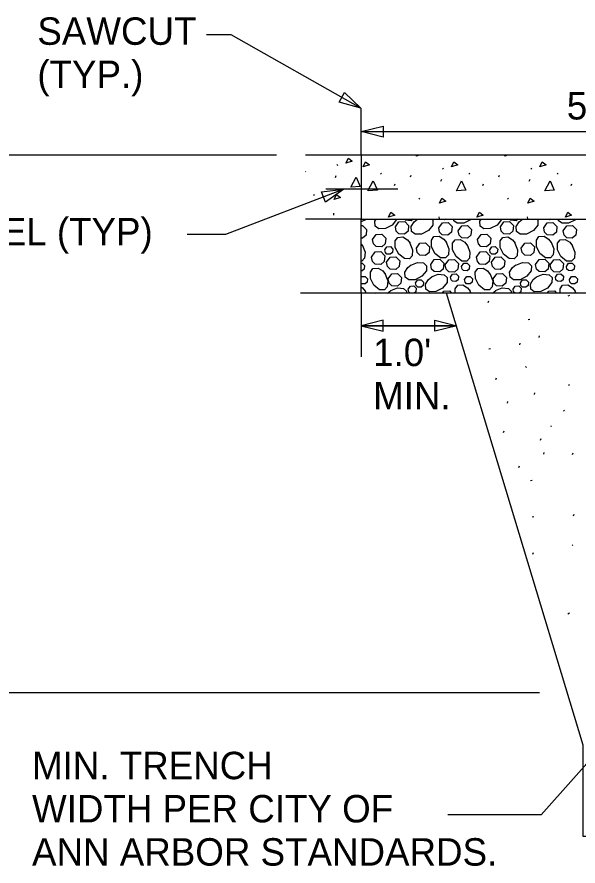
# Model space of a CAD drawing. Extents: x 9992 to 10079.1, y 10009.9 to 10072.5.
# Drawn here: x 10011.77 to 10033.1, y 10036.68 to 10068.99 of the extents above; entities that cross this region are included whole.
import ezdxf

# ---------------------------------------------------------------- set-up
doc = ezdxf.new("R2010")
doc.units = 0
for name, color, linetype in [('Default', 7, 'Continuous'), ('G-ANNO-TEXT', 7, 'Continuous'), ('G-DETL-LINE', 7, 'Continuous'), ('G-DETL-OTLN', 7, 'Continuous'), ('G-DETL-PATT', 7, 'Continuous')]:
    doc.layers.add(name, color=color, linetype=linetype)

# ---------------------------------------------------------------- blocks, each defined once
blk = doc.blocks.new('TERARR')
at = {"layer": 'Default'}
blk.add_lwpolyline([(-0.667, 0.167), (0, 0), (-0.667, -0.167)], close=True, dxfattribs=at)

msp = doc.modelspace()

# ---------------------------------------------------------------- linework, layer by layer
at = {"layer": 'Default'}
for p, q in [((10022.737, 10063.09), (10022.744, 10063.106)), ((10031.165, 10061.379), (10031.172, 10061.312))]:
    msp.add_line(p, q, dxfattribs=at)
for points in [[(10026.952, 10063.687), (10026.959, 10063.733)], [(10027.053, 10063.733), (10026.959, 10063.69)], [(10026.986, 10061.285), (10027.007, 10061.294)], [(10030.818, 10061.294), (10030.747, 10061.234), (10030.533, 10061.25), (10030.488, 10061.294)], [(10030.974, 10061.285), (10030.996, 10061.294)], [(10032.049, 10061.294), (10032.013, 10061.264), (10031.799, 10061.279), (10031.784, 10061.294)], [(10024.858, 10060.348), (10024.909, 10060.285)], [(10025.417, 10058.479), (10025.548, 10058.486), (10025.555, 10058.479)], [(10029.405, 10058.479), (10029.536, 10058.486), (10029.543, 10058.479)]]:
    msp.add_lwpolyline(points, dxfattribs=at)
at = {"layer": 'G-ANNO-TEXT'}
for p, q in [((10024.858, 10063.733), (10024.858, 10065.518)), ((10024.858, 10064.626), (10048.203, 10064.626)), ((9996.263, 10063.735), (10021.636, 10063.735)), ((10024.858, 10063.733), (10022.737, 10063.733)), ((10024.858, 10061.294), (10022.737, 10061.294)), ((10024.858, 10058.479), (10022.551, 10058.479)), ((10024.858, 10058.479), (10024.858, 10056.06)), ((10028.49, 10057.236), (10024.858, 10057.236)), ((10024.858, 10057.236), (10028.383, 10057.236)), ((9996.009, 10043.279), (10031.629, 10043.279))]:
    msp.add_line(p, q, dxfattribs=at)
for points in [[(10024.843, 10065.517), (10019.914, 10068.31), (10018.978, 10068.31)], [(10024.198, 10062.439), (10019.699, 10060.708), (10018.236, 10060.708)], [(10034.052, 10041.283), (10031.691, 10038.635), (10028.143, 10038.635)]]:
    msp.add_lwpolyline(points, dxfattribs=at)
at = {"layer": 'G-DETL-LINE'}
msp.add_line((10026.251, 10062.439), (10023.514, 10062.439), dxfattribs=at)
msp.add_lwpolyline([(10024.858, 10061.294), (10048.226, 10061.294), (10048.226, 10058.479), (10024.858, 10058.479)], close=True, dxfattribs=at)
at = {"layer": 'G-DETL-OTLN'}
msp.add_lwpolyline([(10024.858, 10061.294), (10048.203, 10061.294), (10048.203, 10063.733), (10024.858, 10063.733)], close=True, dxfattribs=at)
msp.add_lwpolyline([(10045.467, 10058.479), (10040.274, 10041.283), (10040.274, 10037.801), (10033.297, 10037.801), (10033.297, 10041.283), (10028.104, 10058.479)], dxfattribs=at)
at = {"layer": 'G-DETL-PATT'}
for p, q in [((10023.934, 10063.374), (10023.964, 10063.33)), ((10027.943, 10063.235), (10027.973, 10063.19)), ((10031.303, 10063.235), (10031.333, 10063.19)), ((10023.877, 10062.883), (10023.907, 10062.95)), ((10025.589, 10063.045), (10025.618, 10063.001)), ((10026.723, 10062.899), (10026.753, 10062.966)), ((10027.887, 10062.744), (10027.917, 10062.811)), ((10028.948, 10063.045), (10028.978, 10063.001)), ((10030.083, 10062.899), (10030.113, 10062.966)), ((10031.246, 10062.744), (10031.276, 10062.811)), ((10032.307, 10063.045), (10032.337, 10063.001)), ((10026.119, 10062.572), (10026.149, 10062.639)), ((10029.479, 10062.572), (10029.509, 10062.639)), ((10032.838, 10062.572), (10032.868, 10062.639)), ((10023.042, 10062.234), (10023.072, 10062.189)), ((10027.052, 10062.095), (10027.081, 10062.05)), ((10030.411, 10062.095), (10030.441, 10062.05)), ((10023.796, 10061.518), (10023.804, 10061.451)), ((10027.806, 10061.379), (10027.813, 10061.312)), ((10032.774, 10058.393), (10032.711, 10058.362)), ((10029.681, 10058.122), (10029.702, 10058.185)), ((10031.269, 10057.474), (10031.204, 10057.46)), ((10031.616, 10056.787), (10031.637, 10056.85)), ((10029.774, 10056.363), (10029.71, 10056.349)), ((10030.882, 10056.514), (10030.903, 10056.577)), ((10031.135, 10055.654), (10031.103, 10055.685)), ((10029.974, 10055.198), (10029.995, 10055.261)), ((10032.774, 10054.968), (10032.743, 10055)), ((10031.44, 10054.623), (10031.461, 10054.686)), ((10030.413, 10054.292), (10030.434, 10054.355)), ((10032.585, 10053.994), (10032.554, 10054.026)), ((10032.056, 10053.428), (10032.082, 10053.414)), ((10032.082, 10053.414), (10032.094, 10053.4)), ((10030.268, 10053.173), (10030.289, 10053.236)), ((10031.675, 10052.88), (10031.696, 10052.943)), ((10031.792, 10052.354), (10031.813, 10052.417)), ((10032.894, 10052.345), (10032.915, 10052.407)), ((10030.853, 10051.847), (10030.874, 10051.91)), ((10031.357, 10051.346), (10031.292, 10051.332)), ((10031.416, 10049.972), (10031.351, 10049.957)), ((10032.924, 10050.005), (10032.945, 10050.068)), ((10032.9, 10048.876), (10032.869, 10048.907)), ((10031.382, 10048.553), (10031.403, 10048.616)), ((10032.774, 10046.299), (10032.711, 10046.268))]:
    msp.add_line(p, q, dxfattribs=at)
for points in [[(10024.276, 10063.426), (10024.366, 10063.613), (10024.515, 10063.501), (10024.276, 10063.426)], [(10024.926, 10063.287), (10025.016, 10063.474), (10025.165, 10063.362), (10024.926, 10063.287)], [(10028.285, 10063.287), (10028.375, 10063.474), (10028.524, 10063.362), (10028.285, 10063.287)], [(10030.312, 10063.687), (10030.318, 10063.733)], [(10030.412, 10063.733), (10030.319, 10063.69)], [(10031.645, 10063.287), (10031.734, 10063.474), (10031.884, 10063.362), (10031.645, 10063.287)], [(10024.463, 10062.51), (10024.664, 10062.89), (10024.821, 10062.54), (10024.47, 10062.51)], [(10025.113, 10062.371), (10025.314, 10062.751), (10025.471, 10062.401), (10025.12, 10062.371)], [(10028.472, 10062.371), (10028.673, 10062.751), (10028.83, 10062.401), (10028.479, 10062.371)], [(10031.831, 10062.371), (10032.033, 10062.751), (10032.189, 10062.401), (10031.839, 10062.371)], [(10023.825, 10062.04), (10023.915, 10062.226), (10024.064, 10062.115), (10023.825, 10062.04)], [(10027.835, 10061.901), (10027.924, 10062.087), (10028.073, 10061.975), (10027.835, 10061.901)], [(10031.194, 10061.901), (10031.284, 10062.087), (10031.433, 10061.975), (10031.194, 10061.901)], [(10025.897, 10061.368), (10025.987, 10061.554), (10026.136, 10061.442), (10025.897, 10061.368)], [(10029.257, 10061.368), (10029.346, 10061.554), (10029.495, 10061.442), (10029.257, 10061.368)], [(10032.616, 10061.368), (10032.705, 10061.554), (10032.854, 10061.442), (10032.616, 10061.368)], [(10025.043, 10061.294), (10025.024, 10061.27), (10024.858, 10061.187)], [(10026.202, 10061.294), (10026.202, 10061.276), (10026.034, 10061.062), (10025.774, 10060.932), (10025.53, 10060.928), (10025.392, 10061.025), (10025.379, 10061.22), (10025.426, 10061.294)], [(10026.156, 10061.005), (10026.292, 10061.198), (10026.508, 10061.21), (10026.659, 10061.054), (10026.637, 10060.836), (10026.503, 10060.724), (10026.29, 10060.74), (10026.189, 10060.837), (10026.156, 10061.005)], [(10026.83, 10061.294), (10026.758, 10061.234), (10026.545, 10061.25), (10026.499, 10061.294)], [(10027.547, 10061.294), (10027.583, 10061.26), (10027.579, 10061.071), (10027.411, 10060.857), (10027.152, 10060.727), (10026.907, 10060.723), (10026.769, 10060.82), (10026.756, 10061.015), (10026.868, 10061.19), (10026.996, 10061.292)], [(10028.061, 10061.294), (10028.024, 10061.264), (10027.811, 10061.279), (10027.796, 10061.294)], [(10027.805, 10060.967), (10027.941, 10061.16), (10028.157, 10061.172), (10028.307, 10061.016), (10028.286, 10060.798), (10028.152, 10060.687), (10027.938, 10060.702), (10027.838, 10060.799), (10027.805, 10060.967)], [(10029.031, 10061.294), (10029.012, 10061.27), (10028.753, 10061.14), (10028.508, 10061.136), (10028.371, 10061.233), (10028.366, 10061.294)], [(10030.191, 10061.294), (10030.19, 10061.276), (10030.022, 10061.062), (10029.763, 10060.932), (10029.518, 10060.928), (10029.38, 10061.025), (10029.367, 10061.22), (10029.415, 10061.294)], [(10030.145, 10061.005), (10030.28, 10061.198), (10030.497, 10061.21), (10030.647, 10061.054), (10030.625, 10060.836), (10030.492, 10060.724), (10030.278, 10060.74), (10030.177, 10060.837), (10030.145, 10061.005)], [(10031.536, 10061.294), (10031.571, 10061.26), (10031.568, 10061.071), (10031.4, 10060.857), (10031.14, 10060.727), (10030.895, 10060.723), (10030.758, 10060.82), (10030.745, 10061.015), (10030.856, 10061.19), (10030.984, 10061.292)], [(10031.793, 10060.967), (10031.929, 10061.16), (10032.145, 10061.172), (10032.296, 10061.016), (10032.274, 10060.798), (10032.14, 10060.687), (10031.927, 10060.702), (10031.826, 10060.799), (10031.794, 10060.967)], [(10033.02, 10061.294), (10033.001, 10061.27), (10032.741, 10061.14), (10032.497, 10061.136), (10032.359, 10061.233), (10032.355, 10061.294)], [(10024.858, 10061.051), (10024.909, 10061.054), (10025.06, 10060.898), (10025.038, 10060.68), (10024.904, 10060.568), (10024.858, 10060.572)], [(10028.546, 10060.849), (10028.681, 10061.042), (10028.898, 10061.054), (10029.048, 10060.898), (10029.026, 10060.68), (10028.893, 10060.568), (10028.679, 10060.584), (10028.579, 10060.681), (10028.546, 10060.849)], [(10032.534, 10060.849), (10032.67, 10061.042), (10032.886, 10061.054), (10033.037, 10060.898), (10033.015, 10060.68), (10032.881, 10060.568), (10032.668, 10060.584), (10032.567, 10060.681), (10032.534, 10060.849)], [(10025.287, 10060.521), (10025.423, 10060.714), (10025.639, 10060.726), (10025.79, 10060.57), (10025.768, 10060.352), (10025.634, 10060.241), (10025.421, 10060.256), (10025.32, 10060.354), (10025.288, 10060.521)], [(10026.71, 10060.385), (10026.81, 10060.132), (10026.79, 10059.899), (10026.685, 10059.788), (10026.496, 10059.792), (10026.281, 10059.96), (10026.152, 10060.219), (10026.147, 10060.464), (10026.245, 10060.602), (10026.44, 10060.615), (10026.614, 10060.503), (10026.716, 10060.375)], [(10028.087, 10060.418), (10028.188, 10060.164), (10028.168, 10059.932), (10028.062, 10059.821), (10027.873, 10059.824), (10027.659, 10059.992), (10027.529, 10060.252), (10027.525, 10060.497), (10027.622, 10060.634), (10027.817, 10060.647), (10027.992, 10060.536), (10028.094, 10060.408)], [(10028.89, 10060.295), (10028.991, 10060.041), (10028.971, 10059.809), (10028.866, 10059.698), (10028.677, 10059.701), (10028.462, 10059.869), (10028.332, 10060.129), (10028.328, 10060.374), (10028.426, 10060.511), (10028.621, 10060.524), (10028.795, 10060.413), (10028.897, 10060.285)], [(10029.276, 10060.521), (10029.411, 10060.714), (10029.628, 10060.726), (10029.778, 10060.57), (10029.756, 10060.352), (10029.623, 10060.241), (10029.409, 10060.256), (10029.309, 10060.354), (10029.276, 10060.521)], [(10030.698, 10060.385), (10030.799, 10060.132), (10030.779, 10059.899), (10030.673, 10059.788), (10030.484, 10059.792), (10030.27, 10059.96), (10030.14, 10060.219), (10030.136, 10060.464), (10030.234, 10060.602), (10030.428, 10060.615), (10030.603, 10060.503), (10030.705, 10060.375)], [(10032.075, 10060.418), (10032.176, 10060.164), (10032.156, 10059.932), (10032.051, 10059.821), (10031.862, 10059.824), (10031.647, 10059.992), (10031.517, 10060.252), (10031.513, 10060.497), (10031.611, 10060.634), (10031.806, 10060.647), (10031.98, 10060.536), (10032.082, 10060.408)], [(10032.879, 10060.295), (10032.979, 10060.041), (10032.959, 10059.809), (10032.854, 10059.698), (10032.665, 10059.701), (10032.45, 10059.869), (10032.321, 10060.129), (10032.316, 10060.374), (10032.414, 10060.511), (10032.609, 10060.524), (10032.783, 10060.413), (10032.885, 10060.285)], [(10024.902, 10060.295), (10025.003, 10060.041), (10024.983, 10059.809), (10024.877, 10059.698), (10024.858, 10059.698)], [(10025.753, 10060.126), (10025.834, 10060.242), (10025.964, 10060.249), (10026.054, 10060.156), (10026.041, 10060.025), (10025.961, 10059.958), (10025.833, 10059.967), (10025.773, 10060.026), (10025.753, 10060.126)], [(10026.953, 10060.193), (10027.089, 10060.386), (10027.305, 10060.398), (10027.456, 10060.243), (10027.434, 10060.024), (10027.3, 10059.913), (10027.087, 10059.928), (10026.986, 10060.026), (10026.953, 10060.193)], [(10029.741, 10060.126), (10029.823, 10060.242), (10029.953, 10060.249), (10030.043, 10060.156), (10030.03, 10060.025), (10029.95, 10059.958), (10029.821, 10059.967), (10029.761, 10060.026), (10029.741, 10060.126)], [(10030.942, 10060.193), (10031.077, 10060.386), (10031.294, 10060.398), (10031.444, 10060.243), (10031.422, 10060.024), (10031.289, 10059.913), (10031.075, 10059.928), (10030.974, 10060.026), (10030.942, 10060.193)], [(10025.25, 10059.852), (10025.385, 10060.045), (10025.601, 10060.057), (10025.752, 10059.901), (10025.73, 10059.683), (10025.596, 10059.571), (10025.383, 10059.587), (10025.282, 10059.684), (10025.25, 10059.852)], [(10025.822, 10059.66), (10025.958, 10059.853), (10026.174, 10059.866), (10026.324, 10059.71), (10026.303, 10059.491), (10026.169, 10059.38), (10025.955, 10059.395), (10025.855, 10059.493), (10025.822, 10059.66)], [(10029.238, 10059.852), (10029.373, 10060.045), (10029.59, 10060.057), (10029.74, 10059.901), (10029.718, 10059.683), (10029.585, 10059.571), (10029.371, 10059.587), (10029.271, 10059.684), (10029.238, 10059.852)], [(10029.81, 10059.66), (10029.946, 10059.853), (10030.162, 10059.866), (10030.313, 10059.71), (10030.291, 10059.491), (10030.157, 10059.38), (10029.944, 10059.395), (10029.843, 10059.493), (10029.811, 10059.66)], [(10024.858, 10059.618), (10024.892, 10059.62), (10024.983, 10059.527), (10024.97, 10059.396), (10024.889, 10059.329), (10024.858, 10059.331)], [(10026.74, 10059.547), (10026.993, 10059.648), (10027.226, 10059.628), (10027.337, 10059.522), (10027.333, 10059.333), (10027.165, 10059.119), (10026.906, 10058.989), (10026.661, 10058.985), (10026.523, 10059.083), (10026.51, 10059.277), (10026.622, 10059.452), (10026.75, 10059.554)], [(10027.496, 10059.565), (10027.631, 10059.758), (10027.848, 10059.77), (10027.998, 10059.614), (10027.976, 10059.396), (10027.842, 10059.284), (10027.629, 10059.3), (10027.528, 10059.397), (10027.496, 10059.565)], [(10028.053, 10059.557), (10028.189, 10059.75), (10028.405, 10059.762), (10028.555, 10059.606), (10028.534, 10059.387), (10028.4, 10059.276), (10028.186, 10059.292), (10028.086, 10059.389), (10028.053, 10059.557)], [(10028.67, 10059.497), (10028.751, 10059.613), (10028.881, 10059.62), (10028.971, 10059.527), (10028.958, 10059.396), (10028.878, 10059.329), (10028.75, 10059.338), (10028.689, 10059.397), (10028.67, 10059.497)], [(10030.728, 10059.547), (10030.982, 10059.648), (10031.214, 10059.628), (10031.325, 10059.522), (10031.322, 10059.333), (10031.154, 10059.119), (10030.894, 10058.989), (10030.649, 10058.985), (10030.512, 10059.083), (10030.499, 10059.277), (10030.61, 10059.452), (10030.738, 10059.554)], [(10031.484, 10059.565), (10031.619, 10059.758), (10031.836, 10059.77), (10031.986, 10059.614), (10031.964, 10059.396), (10031.831, 10059.284), (10031.617, 10059.3), (10031.517, 10059.397), (10031.484, 10059.565)], [(10032.041, 10059.557), (10032.177, 10059.75), (10032.393, 10059.762), (10032.544, 10059.606), (10032.522, 10059.387), (10032.388, 10059.276), (10032.175, 10059.292), (10032.074, 10059.389), (10032.042, 10059.557)], [(10032.658, 10059.497), (10032.739, 10059.613), (10032.869, 10059.62), (10032.959, 10059.527), (10032.946, 10059.396), (10032.866, 10059.329), (10032.738, 10059.338), (10032.678, 10059.397), (10032.658, 10059.497)], [(10025.767, 10059.205), (10025.868, 10058.951), (10025.848, 10058.718), (10025.742, 10058.608), (10025.553, 10058.611), (10025.339, 10058.779), (10025.209, 10059.039), (10025.205, 10059.283), (10025.302, 10059.421), (10025.497, 10059.434), (10025.672, 10059.322), (10025.774, 10059.194)], [(10025.882, 10059.026), (10026.018, 10059.219), (10026.234, 10059.231), (10026.385, 10059.075), (10026.363, 10058.857), (10026.229, 10058.746), (10026.016, 10058.761), (10025.915, 10058.859), (10025.882, 10059.026)], [(10028.25, 10059.091), (10028.332, 10059.206), (10028.461, 10059.214), (10028.552, 10059.12), (10028.539, 10058.989), (10028.458, 10058.922), (10028.33, 10058.932), (10028.27, 10058.99), (10028.25, 10059.091)], [(10029.756, 10059.205), (10029.856, 10058.951), (10029.836, 10058.718), (10029.731, 10058.608), (10029.542, 10058.611), (10029.327, 10058.779), (10029.197, 10059.039), (10029.193, 10059.283), (10029.291, 10059.421), (10029.486, 10059.434), (10029.66, 10059.322), (10029.762, 10059.194)], [(10029.871, 10059.026), (10030.006, 10059.219), (10030.223, 10059.231), (10030.373, 10059.075), (10030.351, 10058.857), (10030.218, 10058.746), (10030.004, 10058.761), (10029.903, 10058.859), (10029.871, 10059.026)], [(10032.239, 10059.091), (10032.32, 10059.206), (10032.45, 10059.214), (10032.54, 10059.12), (10032.527, 10058.989), (10032.447, 10058.922), (10032.319, 10058.932), (10032.258, 10058.99), (10032.239, 10059.091)], [(10024.858, 10059.084), (10024.877, 10059.111), (10025.007, 10059.118), (10025.097, 10059.025), (10025.084, 10058.894), (10025.004, 10058.827), (10024.876, 10058.836), (10024.858, 10058.853)], [(10026.922, 10058.868), (10027.004, 10058.984), (10027.133, 10058.991), (10027.224, 10058.898), (10027.211, 10058.767), (10027.13, 10058.7), (10027.002, 10058.709), (10026.942, 10058.768), (10026.922, 10058.868)], [(10027.526, 10059.094), (10027.78, 10059.195), (10028.013, 10059.175), (10028.123, 10059.07), (10028.12, 10058.881), (10027.952, 10058.666), (10027.692, 10058.536), (10027.448, 10058.532), (10027.31, 10058.63), (10027.297, 10058.825), (10027.409, 10058.999), (10027.536, 10059.101)], [(10028.784, 10058.995), (10028.865, 10059.111), (10028.995, 10059.118), (10029.085, 10059.025), (10029.072, 10058.894), (10028.992, 10058.827), (10028.864, 10058.836), (10028.804, 10058.895), (10028.784, 10058.995)], [(10030.911, 10058.868), (10030.992, 10058.984), (10031.122, 10058.991), (10031.212, 10058.898), (10031.199, 10058.767), (10031.119, 10058.7), (10030.99, 10058.709), (10030.93, 10058.768), (10030.911, 10058.868)], [(10031.515, 10059.094), (10031.768, 10059.195), (10032.001, 10059.175), (10032.112, 10059.07), (10032.108, 10058.881), (10031.94, 10058.666), (10031.681, 10058.536), (10031.436, 10058.532), (10031.298, 10058.63), (10031.285, 10058.825), (10031.397, 10058.999), (10031.525, 10059.101)], [(10032.772, 10058.995), (10032.854, 10059.111), (10032.983, 10059.118), (10033.074, 10059.025), (10033.061, 10058.894), (10032.98, 10058.827), (10032.852, 10058.836), (10032.792, 10058.895), (10032.772, 10058.995)], [(10024.858, 10058.713), (10024.905, 10058.683), (10025.007, 10058.555)], [(10025, 10058.565), (10025.035, 10058.479)], [(10025.857, 10058.479), (10025.859, 10058.483), (10025.987, 10058.585)], [(10025.977, 10058.578), (10026.231, 10058.679), (10026.463, 10058.658), (10026.574, 10058.553), (10026.573, 10058.479)], [(10026.643, 10058.633), (10026.724, 10058.749), (10026.854, 10058.756), (10026.944, 10058.663), (10026.931, 10058.531), (10026.867, 10058.479)], [(10026.718, 10058.479), (10026.662, 10058.532), (10026.643, 10058.633)], [(10028.429, 10058.479), (10028.426, 10058.644), (10028.524, 10058.782), (10028.719, 10058.795), (10028.893, 10058.683), (10028.995, 10058.555)], [(10028.989, 10058.565), (10029.023, 10058.479)], [(10029.845, 10058.479), (10029.848, 10058.483), (10029.976, 10058.585)], [(10029.965, 10058.578), (10030.219, 10058.679), (10030.452, 10058.658), (10030.562, 10058.553), (10030.561, 10058.479)], [(10030.631, 10058.633), (10030.712, 10058.749), (10030.842, 10058.756), (10030.932, 10058.663), (10030.919, 10058.531), (10030.856, 10058.479)], [(10030.706, 10058.479), (10030.651, 10058.532), (10030.631, 10058.633)], [(10032.417, 10058.479), (10032.415, 10058.644), (10032.512, 10058.782), (10032.707, 10058.795), (10032.882, 10058.683), (10032.984, 10058.555)], [(10032.977, 10058.565), (10033.011, 10058.479)], [(10027.942, 10058.479), (10027.994, 10058.552), (10028.21, 10058.564), (10028.292, 10058.479)], [(10031.931, 10058.479), (10031.982, 10058.552), (10032.198, 10058.564), (10032.281, 10058.479)]]:
    msp.add_lwpolyline(points, dxfattribs=at)

# ---------------------------------------------------------------- block references
at = {"layer": 'G-ANNO-TEXT', "xscale": 1.25}
for p, yscale, rotation in [((10024.843, 10065.517), 1.2500000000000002, -29.53015289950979), ((10024.858, 10064.626), 1.25, 180), ((10024.198, 10062.439), 1.25, 21.046814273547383), ((10024.858, 10057.236), -1.25, 180)]:
    msp.add_blockref('TERARR', p, dxfattribs=dict(at, yscale=yscale, rotation=rotation))
at = {"layer": 'G-ANNO-TEXT', "xscale": 1.25, "yscale": 1.25}
msp.add_blockref('TERARR', (10028.49, 10057.236), dxfattribs=at)

# ---------------------------------------------------------------- texts
at = {"layer": 'G-ANNO-TEXT'}
for s, p in [('SAWCUT', (10012.543, 10067.927)), ('(TYP.)', (10012.543, 10066.283)), ("5.0' MIN.", (10032.671, 10065.086)), ('DOWEL (TYP)', (10007.778, 10060.297)), ("1.0' ", (10025.308, 10055.702)), ('MIN.', (10025.308, 10054.058)), ('MIN. TRENCH ', (10012.341, 10039.985)), ('WIDTH PER CITY OF ', (10012.341, 10038.341)), ('ANN ARBOR STANDARDS.', (10012.341, 10036.697))]:
    msp.add_text(s, height=1.044, dxfattribs=at).set_placement(p)

doc.saveas('drawing.dxf')
